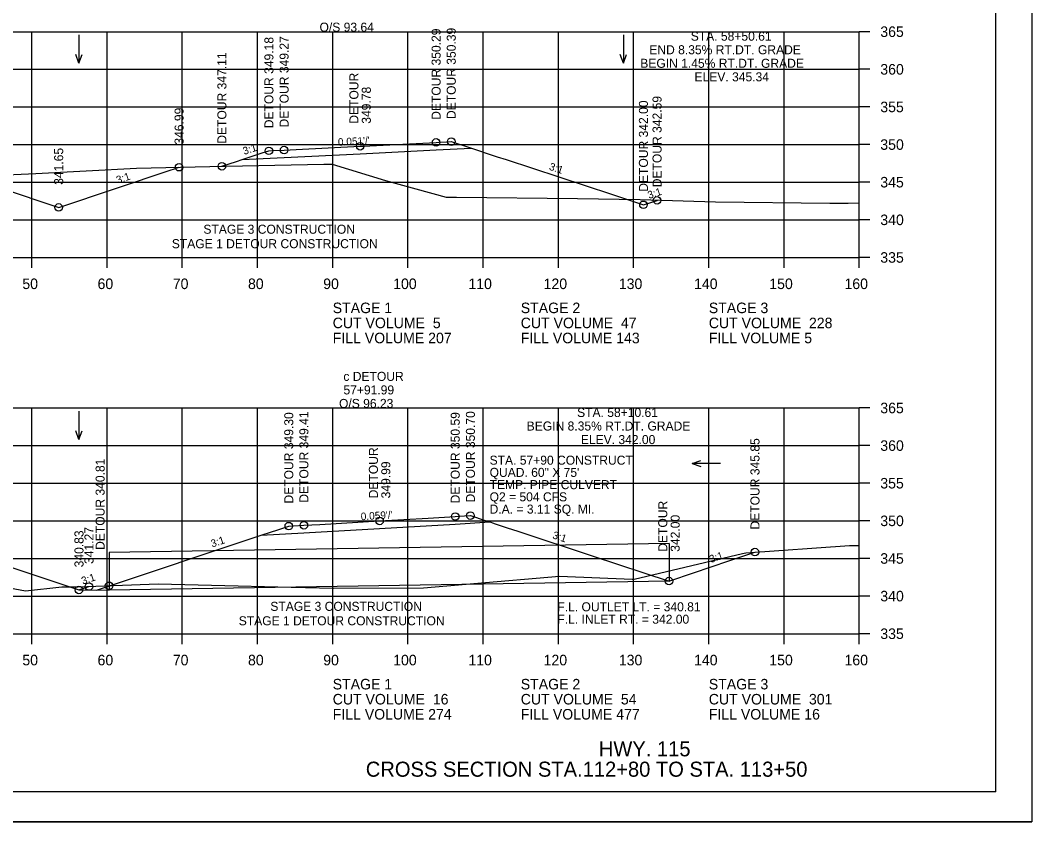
# Model space of a CAD drawing. Extents: x 1630712 to 1632516, y 782146 to 785403.
# Drawn here: x 1632381.4 to 1632515.9, y 784763.3 to 784869.8 of the extents above; entities that cross this region are included whole.
import ezdxf

# ---------------------------------------------------------------- set-up
doc = ezdxf.new("R2010")
doc.units = 0
for name, color, linetype in [('Notes', 7, 'Continuous'), ('R_Axis', 7, 'Continuous'), ('R_Axis Annot', 7, 'Continuous'), ('R_Border', 7, 'Continuous'), ('R_Culvert', 7, 'Continuous'), ('R_Culvert Temporary', 7, 'Continuous'), ('R_Detour Subgrade', 7, 'Continuous'), ('R_Detour Surface', 7, 'Continuous'), ('R_Draft', 7, 'Continuous'), ('R_Exist Surface', 7, 'Continuous'), ('R_Fin Surface', 7, 'Continuous'), ('R_Grid', 7, 'Continuous'), ('R_No Plot', 7, 'Continuous'), ('R_Water Annot', 7, 'Continuous'), ('R_Xsect Elev', 7, 'Continuous'), ('R_Xsect Elev Detour', 7, 'Continuous'), ('R_Xsect Slope', 7, 'Continuous')]:
    doc.layers.add(name, color=color, linetype=linetype)

msp = doc.modelspace()

# ---------------------------------------------------------------- linework, layer by layer
at = {"layer": 'R_Axis'}
for p, q in [((1632492.96, 784838.31), (1632492.96, 784868.31)), ((1632494.36, 784868.31), (1632492.96, 784868.31)), ((1632494.36, 784863.31), (1632492.96, 784863.31)), ((1632494.36, 784858.31), (1632492.96, 784858.31)), ((1632494.36, 784853.31), (1632492.96, 784853.31)), ((1632494.36, 784848.31), (1632492.96, 784848.31)), ((1632494.36, 784843.31), (1632492.96, 784843.31)), ((1632212.96, 784838.31), (1632492.96, 784838.31)), ((1632382.96, 784836.91), (1632382.96, 784838.31)), ((1632392.96, 784836.91), (1632392.96, 784838.31)), ((1632402.96, 784836.91), (1632402.96, 784838.31)), ((1632412.96, 784836.91), (1632412.96, 784838.31)), ((1632422.96, 784836.91), (1632422.96, 784838.31)), ((1632432.96, 784836.91), (1632432.96, 784838.31)), ((1632442.96, 784836.91), (1632442.96, 784838.31)), ((1632452.96, 784836.91), (1632452.96, 784838.31)), ((1632462.96, 784836.91), (1632462.96, 784838.31)), ((1632472.96, 784836.91), (1632472.96, 784838.31)), ((1632482.96, 784836.91), (1632482.96, 784838.31)), ((1632492.96, 784836.91), (1632492.96, 784838.31)), ((1632494.36, 784838.31), (1632492.96, 784838.31)), ((1632492.96, 784788.31), (1632492.96, 784818.31)), ((1632494.36, 784818.31), (1632492.96, 784818.31)), ((1632494.36, 784813.31), (1632492.96, 784813.31)), ((1632494.36, 784808.31), (1632492.96, 784808.31)), ((1632494.36, 784803.31), (1632492.96, 784803.31)), ((1632494.36, 784798.31), (1632492.96, 784798.31)), ((1632494.36, 784793.31), (1632492.96, 784793.31)), ((1632212.96, 784788.31), (1632492.96, 784788.31)), ((1632382.96, 784786.91), (1632382.96, 784788.31)), ((1632392.96, 784786.91), (1632392.96, 784788.31)), ((1632402.96, 784786.91), (1632402.96, 784788.31)), ((1632412.96, 784786.91), (1632412.96, 784788.31)), ((1632422.96, 784786.91), (1632422.96, 784788.31)), ((1632432.96, 784786.91), (1632432.96, 784788.31)), ((1632442.96, 784786.91), (1632442.96, 784788.31)), ((1632452.96, 784786.91), (1632452.96, 784788.31)), ((1632462.96, 784786.91), (1632462.96, 784788.31)), ((1632472.96, 784786.91), (1632472.96, 784788.31)), ((1632482.96, 784786.91), (1632482.96, 784788.31)), ((1632492.96, 784786.91), (1632492.96, 784788.31)), ((1632494.36, 784788.31), (1632492.96, 784788.31))]:
    msp.add_line(p, q, dxfattribs=at)
at = {"layer": 'R_Border'}
for q in [(1632511.14, 784972.77), (1632194.96, 784767.31)]:
    msp.add_line((1632511.14, 784767.31), q, dxfattribs=at)
at = {"layer": 'R_Culvert'}
for p, q in [((1632467.67, 784800.31), (1632393.23, 784799.12)), ((1632467.67, 784800.31), (1632467.67, 784795.31)), ((1632393.23, 784799.12), (1632393.23, 784794.12)), ((1632467.67, 784795.31), (1632393.23, 784794.12))]:
    msp.add_line(p, q, dxfattribs=at)
at = {"layer": 'R_Detour Subgrade'}
for points in [[(1632410.92, 784851.31), (1632416.5, 784851.58), (1632426.61, 784852.08), (1632436.71, 784852.6), (1632441.36, 784852.84)], [(1632413.47, 784801.4), (1632419.13, 784801.72), (1632429.19, 784802.3), (1632439.25, 784802.89), (1632443.84, 784803.16)]]:
    msp.add_lwpolyline(points, dxfattribs=at)
at = {"layer": 'R_Detour Surface'}
msp.add_line((1632389.23, 784794.13), (1632393.23, 784794.12), dxfattribs=at)
for points in [[(1632408.23, 784850.42), (1632410.16, 784851.06), (1632410.92, 784851.31), (1632413.59, 784852.19), (1632414.48, 784852.48), (1632414.93, 784852.5), (1632416.5, 784852.58), (1632418.12, 784852.66), (1632426.59, 784853.08), (1632426.61, 784853.08), (1632427.03, 784853.1), (1632436.71, 784853.6), (1632437.07, 784853.61), (1632438.2, 784853.67), (1632438.72, 784853.7), (1632441.26, 784852.87), (1632441.36, 784852.84), (1632441.42, 784852.81), (1632441.96, 784852.64), (1632444.04, 784851.95), (1632444.81, 784851.7), (1632446.01, 784851.31), (1632460.02, 784846.7), (1632464.27, 784845.31), (1632464.4, 784845.35), (1632466.08, 784845.9), (1632466.16, 784845.93)], [(1632391.54, 784794.12), (1632413.47, 784801.4), (1632415.8, 784802.17), (1632417.12, 784802.61), (1632417.73, 784802.64), (1632419.13, 784802.72), (1632421.24, 784802.84), (1632429.19, 784803.3), (1632435.64, 784803.68), (1632439.25, 784803.89), (1632440.5, 784803.97), (1632441.27, 784804.01), (1632443.24, 784803.36), (1632443.84, 784803.16), (1632444.34, 784803), (1632444.44, 784802.97), (1632446.15, 784802.4), (1632447.58, 784801.93), (1632457.45, 784798.68), (1632467.67, 784795.31), (1632467.78, 784795.34), (1632470.93, 784796.39), (1632475.61, 784797.98), (1632479.1, 784799.16)]]:
    msp.add_lwpolyline(points, dxfattribs=at)
at = {"layer": 'R_Exist Surface'}
for points in [[(1632371.82, 784848.92), (1632383.48, 784849.48), (1632396.86, 784850.18), (1632406.62, 784850.38), (1632421.78, 784850.7), (1632422.88, 784850.71), (1632429.99, 784848.53), (1632438.04, 784846.32), (1632439.02, 784846.3), (1632439.42, 784846.3), (1632455.49, 784846.16), (1632463.82, 784846), (1632473.86, 784845.7), (1632489.03, 784845.51), (1632491.48, 784845.54), (1632492.96, 784845.55)], [(1632373.84, 784795.54), (1632382.12, 784794.01), (1632386.96, 784794.56), (1632389.08, 784794.52), (1632399.77, 784794.92), (1632406.86, 784794.75), (1632417.45, 784794.5), (1632423.12, 784794.35), (1632435.04, 784794.41), (1632439.67, 784794.79), (1632441.74, 784794.99), (1632453.12, 784795.97), (1632462.79, 784795.57), (1632462.87, 784795.57), (1632463.04, 784795.57), (1632477.42, 784798.96), (1632477.88, 784799.07), (1632491.65, 784800.02), (1632492.85, 784800.03), (1632492.96, 784800.03)]]:
    msp.add_lwpolyline(points, dxfattribs=at)
at = {"layer": 'R_Fin Surface'}
for points in [[(1632285.78, 784850.33), (1632290.64, 784848.71), (1632296.96, 784850.82), (1632310.79, 784854.27), (1632314.96, 784855.32), (1632320.96, 784855.56), (1632332.96, 784855.8), (1632344.96, 784855.56), (1632350.96, 784855.32), (1632355.14, 784854.27), (1632368.96, 784850.82), (1632385.36, 784845.35), (1632385.37, 784845.35), (1632385.51, 784845.3), (1632386.53, 784844.96), (1632401.47, 784849.94), (1632401.78, 784850.05), (1632401.78, 784850.05), (1632402.54, 784850.3)], [(1632270.62, 784798.66), (1632271.44, 784798.39), (1632280.45, 784795.39), (1632281.94, 784795.88), (1632296.96, 784800.89), (1632310.78, 784804.34), (1632314.96, 784805.39), (1632320.96, 784805.63), (1632332.96, 784805.87), (1632344.96, 784805.63), (1632350.96, 784805.39), (1632355.15, 784804.34), (1632368.96, 784800.89), (1632389.23, 784794.13), (1632390.56, 784794.58)]]:
    msp.add_lwpolyline(points, dxfattribs=at)
at = {"layer": 'R_Grid'}
for p, q in [((1632212.96, 784868.31), (1632492.96, 784868.31)), ((1632382.96, 784838.31), (1632382.96, 784868.31)), ((1632392.96, 784838.31), (1632392.96, 784868.31)), ((1632402.96, 784838.31), (1632402.96, 784868.31)), ((1632412.96, 784838.31), (1632412.96, 784868.31)), ((1632422.96, 784838.31), (1632422.96, 784868.31)), ((1632432.96, 784838.31), (1632432.96, 784868.31)), ((1632442.96, 784838.31), (1632442.96, 784868.31)), ((1632452.96, 784838.31), (1632452.96, 784868.31)), ((1632462.96, 784838.31), (1632462.96, 784868.31)), ((1632472.96, 784838.31), (1632472.96, 784868.31)), ((1632482.96, 784838.31), (1632482.96, 784868.31)), ((1632492.96, 784838.31), (1632492.96, 784868.31)), ((1632212.96, 784863.31), (1632492.96, 784863.31)), ((1632212.96, 784858.31), (1632492.96, 784858.31)), ((1632212.96, 784853.31), (1632492.96, 784853.31)), ((1632212.96, 784848.31), (1632492.96, 784848.31)), ((1632212.96, 784843.31), (1632492.96, 784843.31)), ((1632212.96, 784838.31), (1632492.96, 784838.31)), ((1632212.96, 784818.31), (1632492.96, 784818.31)), ((1632382.96, 784788.31), (1632382.96, 784818.31)), ((1632392.96, 784788.31), (1632392.96, 784818.31)), ((1632402.96, 784788.31), (1632402.96, 784818.31)), ((1632412.96, 784788.31), (1632412.96, 784818.31)), ((1632422.96, 784788.31), (1632422.96, 784818.31)), ((1632432.96, 784788.31), (1632432.96, 784818.31)), ((1632442.96, 784788.31), (1632442.96, 784818.31)), ((1632452.96, 784788.31), (1632452.96, 784818.31)), ((1632462.96, 784788.31), (1632462.96, 784818.31)), ((1632472.96, 784788.31), (1632472.96, 784818.31)), ((1632482.96, 784788.31), (1632482.96, 784818.31)), ((1632492.96, 784788.31), (1632492.96, 784818.31)), ((1632212.96, 784813.31), (1632492.96, 784813.31)), ((1632212.96, 784808.31), (1632492.96, 784808.31)), ((1632212.96, 784803.31), (1632492.96, 784803.31)), ((1632212.96, 784798.31), (1632492.96, 784798.31)), ((1632212.96, 784793.31), (1632492.96, 784793.31)), ((1632212.96, 784788.31), (1632492.96, 784788.31))]:
    msp.add_line(p, q, dxfattribs=at)
at = {"layer": 'R_No Plot'}
msp.add_line((1632182.56, 784763.33), (1632515.9, 784763.33), dxfattribs=at)
msp.add_lwpolyline([(1632182.56, 784976.66), (1632515.9, 784976.66), (1632515.9, 784763.32), (1632182.56, 784763.32)], close=True, dxfattribs=at)
for centre in [(1632436.71, 784853.6), (1632438.72, 784853.7), (1632414.48, 784852.48), (1632416.5, 784852.58), (1632426.61, 784853.08), (1632402.54, 784850.3), (1632408.23, 784850.42), (1632466.08, 784845.9), (1632386.53, 784844.96), (1632464.27, 784845.31), (1632439.25, 784803.89), (1632441.27, 784804.01), (1632417.12, 784802.61), (1632419.13, 784802.72), (1632429.19, 784803.3), (1632479.1, 784799.16), (1632390.56, 784794.58), (1632393.23, 784794.68), (1632467.67, 784795.31), (1632389.23, 784794.13)]:
    msp.add_circle(centre, 0.5, dxfattribs=at)
at = {"layer": 'R_Water Annot'}
for p, q in [((1632389.23, 784867.88), (1632389.23, 784864.11)), ((1632461.61, 784867.88), (1632461.61, 784864.11)), ((1632389.23, 784864.11), (1632388.81, 784865.26)), ((1632389.23, 784864.11), (1632389.65, 784865.26)), ((1632461.61, 784864.11), (1632461.19, 784865.26)), ((1632461.61, 784864.11), (1632462.03, 784865.26)), ((1632389.23, 784817.88), (1632389.23, 784814.11)), ((1632389.23, 784814.11), (1632388.81, 784815.26)), ((1632389.23, 784814.11), (1632389.65, 784815.26)), ((1632470.74, 784810.93), (1632471.89, 784811.35)), ((1632474.51, 784810.93), (1632470.74, 784810.93)), ((1632470.74, 784810.93), (1632471.89, 784810.51))]:
    msp.add_line(p, q, dxfattribs=at)

# ---------------------------------------------------------------- texts
at = {"layer": 'Notes'}
for s, p in [('O/S 93.64', (1632421.21, 784868.31)), ('STA. 58+50.61', (1632470.56, 784867.11)), ('END 8.35% RT.DT. GRADE', (1632465.05, 784865.31)), ('BEGIN 1.45% RT.DT. GRADE', (1632463.85, 784863.51)), ('ELEV. 345.34', (1632471.06, 784861.71)), ('STAGE 3 CONSTRUCTION', (1632405.77, 784841.46)), ('STAGE 1 DETOUR CONSTRUCTION', (1632401.57, 784839.54)), ('c DETOUR', (1632424.38, 784821.91)), ('57+91.99', (1632424.39, 784820.11)), ('O/S 96.23', (1632423.8, 784818.31)), ('STA. 58+10.61', (1632455.45, 784817.11)), ('BEGIN 8.35% RT.DT. GRADE', (1632448.75, 784815.31)), ('ELEV. 342.00', (1632455.95, 784813.51)), ('STAGE 3 CONSTRUCTION', (1632414.67, 784791.35)), ('F.L. OUTLET LT. = 340.81', (1632452.83, 784791.29)), ('STAGE 1 DETOUR CONSTRUCTION', (1632410.47, 784789.43)), ('F.L. INLET RT. = 342.00', (1632452.83, 784789.64))]:
    msp.add_text(s, height=1.2, dxfattribs=at).set_placement(p)
at = {"layer": 'R_Axis Annot'}
for s, p in [('365', (1632495.76, 784867.61)), ('360', (1632495.76, 784862.61)), ('355', (1632495.76, 784857.61)), ('350', (1632495.76, 784852.61)), ('345', (1632495.76, 784847.61)), ('340', (1632495.76, 784842.61)), ('335', (1632495.76, 784837.61)), ('50', (1632381.7, 784834.11)), ('60', (1632391.7, 784834.11)), ('70', (1632401.7, 784834.11)), ('80', (1632411.7, 784834.11)), ('90', (1632421.7, 784834.11)), ('100', (1632431, 784834.11)), ('110', (1632441, 784834.11)), ('120', (1632451, 784834.11)), ('130', (1632461, 784834.11)), ('140', (1632471, 784834.11)), ('150', (1632481, 784834.11)), ('160', (1632491, 784834.11)), ('STAGE 1', (1632422.96, 784830.91)), ('STAGE 2', (1632447.96, 784830.91)), ('STAGE 3', (1632472.96, 784830.91)), ('CUT VOLUME  5', (1632422.96, 784828.91)), ('CUT VOLUME  47', (1632447.96, 784828.91)), ('CUT VOLUME  228', (1632472.96, 784828.91)), ('FILL VOLUME 207', (1632422.96, 784826.91)), ('FILL VOLUME 143', (1632447.96, 784826.91)), ('FILL VOLUME 5', (1632472.96, 784826.91)), ('365', (1632495.76, 784817.61)), ('360', (1632495.76, 784812.61)), ('355', (1632495.76, 784807.61)), ('350', (1632495.76, 784802.61)), ('345', (1632495.76, 784797.61)), ('340', (1632495.76, 784792.61)), ('335', (1632495.76, 784787.61)), ('50', (1632381.7, 784784.11)), ('60', (1632391.7, 784784.11)), ('70', (1632401.7, 784784.11)), ('80', (1632411.7, 784784.11)), ('90', (1632421.7, 784784.11)), ('100', (1632431, 784784.11)), ('110', (1632441, 784784.11)), ('120', (1632451, 784784.11)), ('130', (1632461, 784784.11)), ('140', (1632471, 784784.11)), ('150', (1632481, 784784.11)), ('160', (1632491, 784784.11)), ('STAGE 1', (1632422.96, 784780.91)), ('STAGE 2', (1632447.96, 784780.91)), ('STAGE 3', (1632472.96, 784780.91)), ('CUT VOLUME  16', (1632422.96, 784778.91)), ('CUT VOLUME  54', (1632447.96, 784778.91)), ('CUT VOLUME  301', (1632472.96, 784778.91)), ('FILL VOLUME 274', (1632422.96, 784776.91)), ('FILL VOLUME 477', (1632447.96, 784776.91)), ('FILL VOLUME 16', (1632472.96, 784776.91))]:
    msp.add_text(s, height=1.4, dxfattribs=at).set_placement(p)
at = {"layer": 'R_Culvert Temporary'}
for s, p in [('STA. 57+90 CONSTRUCT', (1632443.82, 784810.77)), ('QUAD. 60" X 75\'', (1632443.82, 784809.15)), ('TEMP. PIPE CULVERT', (1632443.82, 784807.52)), ('Q2 = 504 CFS ', (1632443.82, 784805.9)), ('D.A. = 3.11 SQ. MI.', (1632443.82, 784804.27))]:
    msp.add_text(s, height=1.2, dxfattribs=at).set_placement(p)
at = {"layer": 'R_Draft'}
for s, p in [('HWY. 115', (1632458.34, 784772.02)), ('CROSS SECTION STA.112+80 TO STA. 113+50', (1632427.36, 784769.31))]:
    msp.add_text(s, height=2, dxfattribs=at).set_placement(p)
at = {"layer": 'R_Xsect Elev'}
for s, p in [('346.99', (1632403.14, 784853.3)), ('341.65', (1632387.13, 784847.96)), ('340.83', (1632389.83, 784797.13)), ('341.27', (1632391.16, 784797.58))]:
    msp.add_text(s, height=1.2, rotation=90, dxfattribs=at).set_placement(p)
at = {"layer": 'R_Xsect Elev Detour'}
for s, p in [('DETOUR 349.18', (1632415.08, 784855.48)), ('DETOUR 349.27', (1632417.1, 784855.58)), ('DETOUR 350.29', (1632437.31, 784856.6)), ('DETOUR 350.39', (1632439.32, 784856.7)), ('DETOUR 347.11', (1632408.83, 784853.42)), ('DETOUR', (1632426.38, 784856.08)), ('349.78', (1632428.03, 784856.08)), ('DETOUR 342.59', (1632466.68, 784847.64)), ('DETOUR 342.00', (1632464.87, 784847.04)), ('DETOUR 349.41', (1632419.73, 784805.72)), ('DETOUR 350.70', (1632441.87, 784805.75)), ('DETOUR 349.30', (1632417.72, 784805.61)), ('DETOUR 350.59', (1632439.85, 784805.63)), ('DETOUR 345.85', (1632479.7, 784802.16)), ('DETOUR', (1632428.97, 784806.3)), ('DETOUR 340.81', (1632392.64, 784799.45)), ('349.99', (1632430.62, 784806.3)), ('  DETOUR', (1632467.44, 784798.31)), ('  342.00', (1632469.09, 784798.31))]:
    msp.add_text(s, height=1.2, rotation=90, dxfattribs=at).set_placement(p)
at = {"layer": 'R_Xsect Slope'}
for s, rotation, p in [("0.051'/'", 2.913, (1632423.68, 784853.14)), ('3:1', 18.2889, (1632411.2, 784851.93)), ('3:1', 341.8133, (1632451.65, 784849.98)), ('3:1', 18.4349, (1632394.37, 784848.1)), ('3:1', 18.1926, (1632465.02, 784846.08)), ("0.059'/'", 3.3626, (1632426.72, 784803.39)), ('3:1', 341.7528, (1632452.1, 784801.01)), ('3:1', 18.3652, (1632406.94, 784799.77)), ('3:1', 18.6182, (1632473.22, 784797.71)), ('3:1', 18.4349, (1632389.74, 784794.83))]:
    msp.add_text(s, height=1, rotation=rotation, dxfattribs=at).set_placement(p)

doc.saveas('drawing.dxf')
